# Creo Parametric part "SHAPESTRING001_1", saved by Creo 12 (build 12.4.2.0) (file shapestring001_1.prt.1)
Units: Custom; MM, KILOGRAM, SECS

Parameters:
  PTC_WM_ITERATION = "0"
  PTC_WM_VERSION = "-.0"
  PTC_WM_LIFECYCLE_STATE = "In Work"
  PTC_WM_LIFECYCLE = "MO_CADDocument"
  PTC_WM_CREATED_BY = "Maximilian Roepper (Z0017RMS: MO)"
  PTC_WM_CREATED_ON = "18-Sep-26 11:36:42 AM"
  PTC_WM_MODIFIED_BY = "Maximilian Roepper (Z0017RMS: MO)"
  PTC_WM_MODIFIED_ON = "18-Sep-26 11:36:46 AM"
  PDMLINKNUMBER = "PDM000071455097"
  PTC_WM_NAME = "shapestring001_1.prt"
  PTC_WM_NUMBER = "PDM000071455097"

Other parameters: WEIGHT, WEIGHT_FACTOR, WEIGHT_ADD, _MASS_TEMP, _DIFF_TEMP, MC_ERRORS, SUPPLIER

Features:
  1. coordinate system
  2. datum plane "PRT_YZ"
  3. datum plane "PRT_XY"
  4. datum plane "PRT_XZ"
  5. coordinate system
  6. datum axis
  7. datum axis
  8. datum axis
  9. coordinate system
  10. imported feature
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
Other named items: PRT, SIEMENS_MO, DRW_VIEW_ORG, PRT_X, PRT_Y, PRT_Z, CS0, ROUGH_GROB

Layers: 00_STD_CSYS-KSYS, 01_STD_PLANES-EBENEN, 02_STD_AXES-ACHSEN, 03_STD_CSYS-KSYS, 24_IMPORT_FEAT-IMPORT_KE, WHITE

Surfaces: 1 plane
